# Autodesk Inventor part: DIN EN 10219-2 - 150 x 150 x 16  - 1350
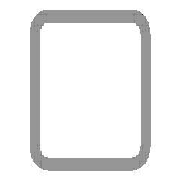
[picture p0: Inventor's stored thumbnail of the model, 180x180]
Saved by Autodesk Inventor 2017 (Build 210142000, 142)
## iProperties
_CCFamilyMember: 76
_CCFamilyDisplayName: DIN EN 10219-2 (Square Hollow Section - Cold Formed) - Cold formed welded structural hollow sections of non-alloy and fine grain structural steel
_FrameMemberDoc: Frame Member File
_Version: 15.0.0
_GetPNFromCC: 1
Created: 2017-11
Part Number: DIN EN 10219-2 - 150 x 150 x 16  - 1350
Material: Steel, Mild
Description: Cold formed welded structural hollow sections of non-alloy and fine grain structural steel
Document SubType Name: Modeling
Standard: DIN
Designer: iusti
Standard Revision: 2006-07
Standards Organization: DIN
Language: en-US
Size Designation: 150 x 150 x 16
Categories: <MemberInstance><Categories><Category DisplayName="Structural Shapes" InternalName="089c4875-fa83-4c05-b084-43b9cc11f5ed" Mnemonic="GRDR"><CategoryParameter Dis
Stock Number: 150 x 150 x 16
Mass: 79240 g
Surface Area: 12767.4 cm^2
Volume: 10094.3 cm^3
Density: 7.85 g/cm^3
Appearance: Semi-Polished
IsCustomPart: 1
G_L: 1350.000 mm
G_W: 150.000 mm
G_H: 150.000 mm
+31784DCB-49BB-4333-A68A-9EECAC31F171+CUTDETAIL1: Cut
+064F332C-0C92-447C-A0DA-B9F728113934+CUTDETAIL2: Cut
Author: iusti
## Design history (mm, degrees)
node "Start plane"
node "End plane"
sketch "Sketch"
  geometry: L1 (-75, -27)-(-75, 27); L2 (-27, 75)-(27, 75); L3 (75, 27)-(75, -27); L4 (27, -75)-(-27, -75); L5 (-27, 59)-(27, 59); L6 (59, 27)-(59, -27); L7 (27, -59)-(-27, -59); L8 (-59, -27)-(-59, 27); L9 (0, 118.918)-(0, -118.918) reference; L10 (-118.918, 0)-(118.918, 0) reference; A1 r 48 centre (-27, -27) between (-75, -27) and (-27, -75); A2 r 48 centre (-27, 27) between (-27, 75) and (-75, 27); A3 r 48 centre (27, 27) between (75, 27) and (27, 75); A4 r 48 centre (27, -27) between (27, -75) and (75, -27); A5 r 32 centre (-27, 27) between (-27, 59) and (-59, 27); A6 r 32 centre (27, 27) between (59, 27) and (27, 59); A7 r 32 centre (27, -27) between (27, -59) and (59, -27); A8 r 32 centre (-27, -27) between (-59, -27) and (-27, -59)
  constraints: 16 end point, 16 point on circle, 8 centre point, 8 tangent, 4 parallel, 3 equal radius, 2 perpendicular, 7 other
  dimensions: "d7" = 48 radius of A1 (= G_IR); "d10" = 150 distance between parallel lines of L2 L4 (= G_H); "d11" = 150 distance between parallel lines of L1 L3 (= G_W); "d12" = 16 distance between parallel lines of L3 L6 (= G_T); "d15" = 75 distance between parallel lines of L2 L10 (= 0.5 x d10); "d16" = 75 distance between parallel lines of L9 L3 (= 0.5 x d11)
extrude "Body" new body sketch "Sketch" stored distance "d3" = 1350 (= G_L); taper "d4" = 0 deg
node "Driven Length"
  sketch "Sketch3"
    geometry: L1 (0, 0)-(10, 0) reference
    constraints: 2 end point, 1 horizontal
  workplane "Work Plane3"
  sketch "Sketch4"
    geometry: L1 (-2, 75)-(12, 75) reference; L2 (-2, 1425)-(12, 1425) reference
    dimensions: "d18" = 1350 distance between parallel lines of L1 L2 (derived)
workplane "Work Plane4"
split "Split1"
workplane "Work Plane5"
split "Split2"
body "Solid1"
other parameters: "G_W" = 150 [user parameter; used in 1 equation term], "G_H" = 150 [user parameter; used in 1 equation term], "G_T" = 16 [user parameter; used in 1 equation term], "G_IR" = 48 [user parameter; used in 1 equation term], "G_L" = 1350 (= d18) [user parameter; used in 1 equation term], "G_OFFSET_START" = -75 [user parameter; used in 1 equation term], "G_OFFSET_END" = -75 [user parameter; used in 1 equation term], "d13" = 75 (= -G_OFFSET_START), "d14" = 1425 (= G_OFFSET_END + B_L), "d17" = 90 deg
